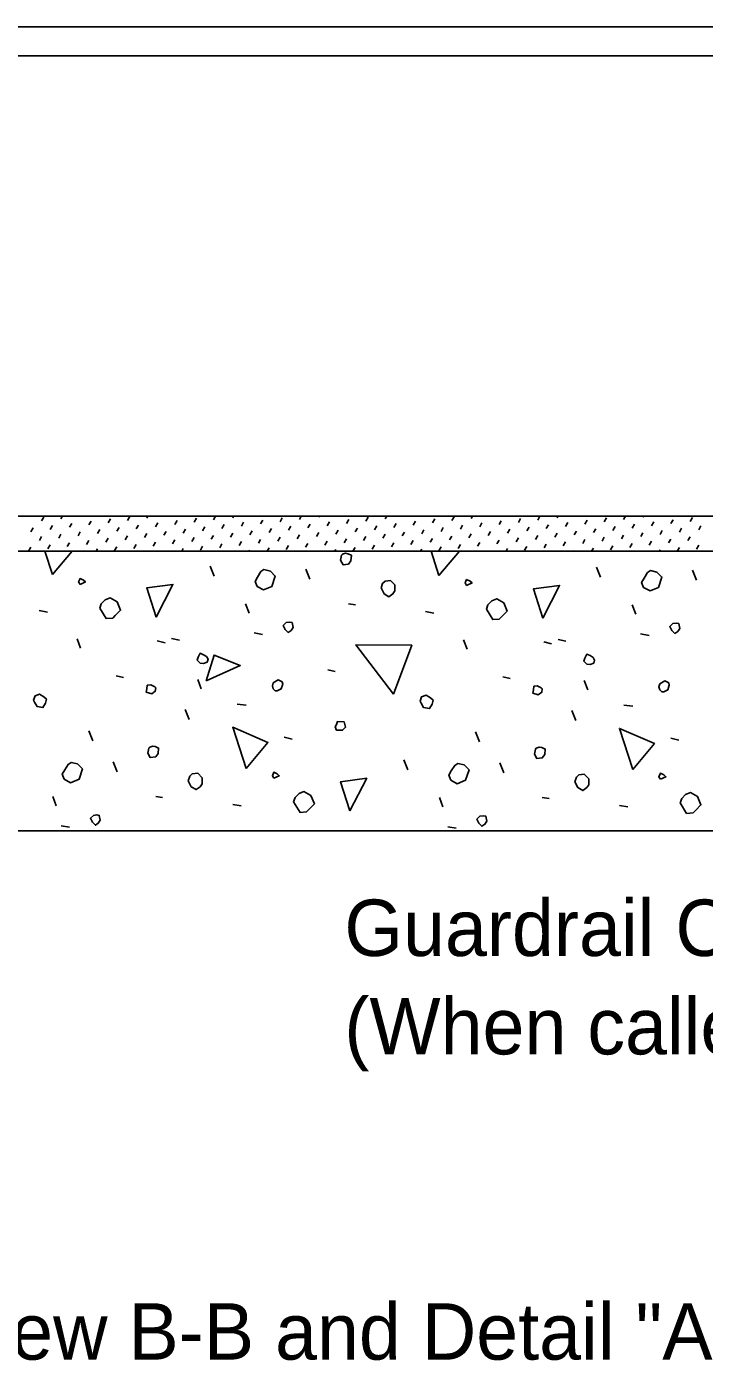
# Model space of a CAD drawing. Extents: x 0.5 to 40.8, y 1 to 25.8.
# Drawn here: x 33.558 to 35.979, y 8.632 to 13.435 of the extents above; entities that cross this region are included whole.
import ezdxf

# ---------------------------------------------------------------- set-up
doc = ezdxf.new("R2010")
doc.units = 0
for name, color, linetype in [('Dimension', 7, 'Continuous'), ('Miscellaneous', 7, 'Continuous'), ('TrafBarrierConc', 7, 'Continuous')]:
    doc.layers.add(name, color=color, linetype=linetype)

msp = doc.modelspace()

# ---------------------------------------------------------------- linework, layer by layer
at = {"layer": 'Miscellaneous'}
for p, q in [((33.6104, 11.6679), (33.6185, 11.6819)), ((33.6796, 11.676), (33.6846, 11.6848)), ((33.7487, 11.6841), (33.7491, 11.6848)), ((33.8484, 11.6617), (33.8565, 11.6757)), ((33.9176, 11.6698), (33.9257, 11.6838)), ((33.9868, 11.6779), (33.9907, 11.6848)), ((34.1556, 11.6636), (34.1637, 11.6776)), ((34.2248, 11.6717), (34.2324, 11.6848)), ((34.2939, 11.6798), (34.2968, 11.6848)), ((34.4628, 11.6654), (34.4709, 11.6794)), ((34.532, 11.6735), (34.5385, 11.6848)), ((34.6011, 11.6816), (34.6029, 11.6848)), ((34.7008, 11.6592), (34.7089, 11.6732)), ((34.77, 11.6673), (34.7781, 11.6813)), ((34.8391, 11.6754), (34.8446, 11.6848)), ((34.9083, 11.6835), (34.909, 11.6848)), ((35.008, 11.6611), (35.0161, 11.6751)), ((35.0772, 11.6692), (35.0853, 11.6832)), ((35.1463, 11.6773), (35.1507, 11.6848)), ((35.3152, 11.663), (35.3233, 11.677)), ((35.3844, 11.6711), (35.3923, 11.6848)), ((35.4535, 11.6792), (35.4568, 11.6848)), ((35.6224, 11.6649), (35.6305, 11.6789)), ((35.6915, 11.673), (35.6984, 11.6848)), ((35.7607, 11.6811), (35.7629, 11.6848)), ((35.8604, 11.6586), (35.8685, 11.6726)), ((35.9296, 11.6667), (35.9377, 11.6807)), ((33.5718, 11.6293), (33.5799, 11.6433)), ((33.6409, 11.6374), (33.649, 11.6514)), ((33.7101, 11.6455), (33.7182, 11.6595)), ((33.7406, 11.615), (33.7487, 11.6289)), ((33.7793, 11.6536), (33.7874, 11.6676)), ((33.8098, 11.6231), (33.8179, 11.6371)), ((33.879, 11.6312), (33.8871, 11.6452)), ((33.9481, 11.6393), (33.9562, 11.6533)), ((34.0173, 11.6474), (34.0254, 11.6614)), ((34.0478, 11.6168), (34.0559, 11.6308)), ((34.0864, 11.6555), (34.0945, 11.6695)), ((34.117, 11.6249), (34.1251, 11.6389)), ((34.1861, 11.633), (34.1942, 11.647)), ((34.2553, 11.6411), (34.2634, 11.6551)), ((34.2858, 11.6106), (34.2939, 11.6246)), ((34.3245, 11.6492), (34.3326, 11.6632)), ((34.355, 11.6187), (34.3631, 11.6327)), ((34.3936, 11.6573), (34.4017, 11.6713)), ((34.4242, 11.6268), (34.4323, 11.6408)), ((34.4933, 11.6349), (34.5014, 11.6489)), ((34.5625, 11.643), (34.5706, 11.657)), ((34.593, 11.6125), (34.6011, 11.6265)), ((34.6317, 11.6511), (34.6398, 11.6651)), ((34.6622, 11.6206), (34.6703, 11.6346)), ((34.7314, 11.6287), (34.7395, 11.6427)), ((34.8005, 11.6368), (34.8086, 11.6508)), ((34.8697, 11.6449), (34.8778, 11.6589)), ((34.9002, 11.6144), (34.9083, 11.6284)), ((34.9388, 11.653), (34.9469, 11.667)), ((34.9694, 11.6225), (34.9775, 11.6365)), ((35.0385, 11.6306), (35.0466, 11.6446)), ((35.1077, 11.6387), (35.1158, 11.6527)), ((35.1769, 11.6468), (35.185, 11.6608)), ((35.2074, 11.6162), (35.2155, 11.6302)), ((35.246, 11.6549), (35.2541, 11.6689)), ((35.2766, 11.6243), (35.2847, 11.6383)), ((35.3457, 11.6324), (35.3538, 11.6464)), ((35.4149, 11.6405), (35.423, 11.6545)), ((35.4841, 11.6487), (35.4922, 11.6626)), ((35.5146, 11.6181), (35.5227, 11.6321)), ((35.5532, 11.6568), (35.5613, 11.6707)), ((35.5837, 11.6262), (35.5918, 11.6402)), ((35.6529, 11.6343), (35.661, 11.6483)), ((35.7221, 11.6424), (35.7302, 11.6564)), ((35.7526, 11.6119), (35.7607, 11.6259)), ((35.7912, 11.6505), (35.7993, 11.6645)), ((35.8218, 11.62), (35.8299, 11.634)), ((35.8909, 11.6281), (35.899, 11.6421)), ((35.9601, 11.6362), (35.9682, 11.6502)), ((33.6023, 11.5987), (33.6104, 11.6127)), ((33.6328, 11.5682), (33.6409, 11.5822)), ((33.6715, 11.6069), (33.6796, 11.6208)), ((33.702, 11.5763), (33.7101, 11.5903)), ((33.7712, 11.5844), (33.7793, 11.5984)), ((33.8403, 11.5925), (33.8484, 11.6065)), ((33.9095, 11.6006), (33.9176, 11.6146)), ((33.94, 11.5701), (33.9481, 11.5841)), ((33.9787, 11.6087), (33.9868, 11.6227)), ((34.0092, 11.5782), (34.0173, 11.5922)), ((34.0783, 11.5863), (34.0864, 11.6003)), ((34.1475, 11.5944), (34.1556, 11.6084)), ((34.178, 11.5639), (34.1861, 11.5779)), ((34.2167, 11.6025), (34.2248, 11.6165)), ((34.2472, 11.572), (34.2553, 11.586)), ((34.3164, 11.5801), (34.3245, 11.5941)), ((34.3855, 11.5882), (34.3936, 11.6022)), ((34.4547, 11.5963), (34.4628, 11.6103)), ((34.4852, 11.5658), (34.4933, 11.5797)), ((34.5239, 11.6044), (34.532, 11.6184)), ((34.5544, 11.5739), (34.5625, 11.5878)), ((34.6236, 11.582), (34.6317, 11.596)), ((34.6927, 11.5901), (34.7008, 11.6041)), ((34.7619, 11.5982), (34.77, 11.6122)), ((34.7924, 11.5676), (34.8005, 11.5816)), ((34.831, 11.6063), (34.8391, 11.6203)), ((34.8616, 11.5757), (34.8697, 11.5897)), ((34.9307, 11.5838), (34.9388, 11.5978)), ((34.9999, 11.5919), (35.008, 11.6059)), ((35.0691, 11.6), (35.0772, 11.614)), ((35.0996, 11.5695), (35.1077, 11.5835)), ((35.1382, 11.6081), (35.1463, 11.6221)), ((35.1688, 11.5776), (35.1769, 11.5916)), ((35.2379, 11.5857), (35.246, 11.5997)), ((35.3071, 11.5938), (35.3152, 11.6078)), ((35.3376, 11.5633), (35.3457, 11.5773)), ((35.3763, 11.6019), (35.3844, 11.6159)), ((35.4068, 11.5714), (35.4149, 11.5854)), ((35.4454, 11.61), (35.4535, 11.624)), ((35.4759, 11.5795), (35.4841, 11.5935)), ((35.5451, 11.5876), (35.5532, 11.6016)), ((35.6143, 11.5957), (35.6224, 11.6097)), ((35.6448, 11.5652), (35.6529, 11.5792)), ((35.6834, 11.6038), (35.6915, 11.6178)), ((35.714, 11.5733), (35.7221, 11.5873)), ((35.7831, 11.5814), (35.7912, 11.5954)), ((35.8523, 11.5895), (35.8604, 11.6035)), ((35.9215, 11.5976), (35.9296, 11.6116)), ((35.952, 11.567), (35.9601, 11.581)), ((33.5637, 11.5601), (33.5718, 11.5741)), ((33.8051, 11.5598), (33.8098, 11.5679)), ((33.8709, 11.562), (33.879, 11.576)), ((34.0467, 11.5598), (34.0478, 11.5617)), ((34.1112, 11.5598), (34.117, 11.5698)), ((34.3528, 11.5598), (34.355, 11.5635)), ((34.4173, 11.5598), (34.4242, 11.5716)), ((34.6589, 11.5598), (34.6622, 11.5654)), ((34.7234, 11.5598), (34.7314, 11.5735)), ((34.965, 11.5598), (34.9694, 11.5673)), ((35.0304, 11.5614), (35.0385, 11.5754)), ((35.2067, 11.5598), (35.2074, 11.5611)), ((35.2711, 11.5598), (35.2766, 11.5692)), ((35.5128, 11.5598), (35.5146, 11.563)), ((35.5772, 11.5598), (35.5837, 11.5711)), ((35.8189, 11.5598), (35.8218, 11.5648)), ((35.8833, 11.5598), (35.8909, 11.5729)), ((34.2268, 11.471), (34.2126, 11.5064)), ((34.5697, 11.4604), (34.5556, 11.4957)), ((35.6092, 11.4675), (35.595, 11.5028)), ((35.9521, 11.4569), (35.938, 11.4922)), ((33.601, 11.3473), (33.631, 11.342)), ((34.3523, 11.3384), (34.3399, 11.372)), ((34.7076, 11.372), (34.7323, 11.3685)), ((34.9834, 11.3437), (35.0134, 11.3384)), ((35.7347, 11.3349), (35.7223, 11.3685)), ((33.7495, 11.2129), (33.7371, 11.2465)), ((34.0747, 11.2483), (34.103, 11.2412)), ((34.3699, 11.2677), (34.4, 11.2624)), ((35.1319, 11.2094), (35.1195, 11.243)), ((35.4571, 11.2447), (35.4854, 11.2377)), ((35.7523, 11.2642), (35.7824, 11.2589)), ((34.0235, 11.2394), (34.0517, 11.2324)), ((35.4059, 11.2359), (35.4341, 11.2288)), ((33.8767, 11.1139), (33.9033, 11.1086)), ((34.1808, 11.0679), (34.1684, 11.1015)), ((34.6333, 11.1351), (34.6599, 11.1298)), ((35.2591, 11.1104), (35.2857, 11.1051)), ((35.5632, 11.0644), (35.5508, 11.098)), ((34.3098, 11.0131), (34.3417, 11.0096)), ((35.6922, 11.0096), (35.7241, 11.0061)), ((34.1384, 10.9583), (34.1242, 10.9937)), ((35.5208, 10.9548), (35.5066, 10.9902)), ((33.7937, 10.8823), (33.7795, 10.9177)), ((35.176, 10.8788), (35.1619, 10.9142)), ((34.4778, 10.8947), (34.5061, 10.8876)), ((35.8602, 10.8912), (35.8885, 10.8841)), ((34.9197, 10.778), (34.9056, 10.8134)), ((33.8803, 10.771), (33.8661, 10.8063)), ((35.2627, 10.7674), (35.2485, 10.8028)), ((33.6628, 10.649), (33.6505, 10.6826)), ((34.0182, 10.6826), (34.0429, 10.679)), ((35.0452, 10.6455), (35.0329, 10.679)), ((35.4006, 10.679), (35.4253, 10.6755)), ((34.2939, 10.6543), (34.324, 10.649)), ((35.6763, 10.6508), (35.7064, 10.6455)), ((33.6805, 10.5783), (33.7106, 10.573)), ((35.0629, 10.5747), (35.093, 10.5694))]:
    msp.add_line(p, q, dxfattribs=at)
for points in [[(33.6487, 11.4763), (33.6215, 11.5598)], [(33.7193, 11.5598), (33.6487, 11.4763)], [(34.6793, 11.5276), (34.6881, 11.5117), (34.7076, 11.5134), (34.7164, 11.5258), (34.7182, 11.5452), (34.7058, 11.5505), (34.697, 11.5523), (34.6864, 11.5488), (34.6828, 11.5452), (34.6793, 11.5276)], [(35.0311, 11.4728), (35.0028, 11.5598)], [(35.1047, 11.5598), (35.0311, 11.4728)], [(34.3806, 11.4339), (34.4035, 11.4215), (34.4336, 11.4339), (34.446, 11.471), (34.4283, 11.4887), (34.4053, 11.494), (34.3947, 11.4869), (34.3823, 11.4675), (34.3735, 11.4516), (34.3806, 11.4339)], [(35.7629, 11.4303), (35.7859, 11.418), (35.816, 11.4303), (35.8284, 11.4675), (35.8107, 11.4851), (35.7877, 11.4904), (35.7771, 11.4834), (35.7647, 11.4639), (35.7559, 11.448), (35.7629, 11.4303)], [(33.7477, 11.4409), (33.7671, 11.4498), (33.7601, 11.4569), (33.7477, 11.4622), (33.7424, 11.4498), (33.7477, 11.4409)], [(34.0199, 11.3243), (33.9863, 11.4286), (34.08, 11.4409), (34.0199, 11.3243)], [(34.8243, 11.4286), (34.8349, 11.4074), (34.8525, 11.3968), (34.8667, 11.4074), (34.8738, 11.418), (34.8738, 11.4392), (34.8579, 11.4551), (34.8384, 11.4533), (34.8296, 11.4445), (34.8243, 11.4286)], [(35.1301, 11.4374), (35.1495, 11.4463), (35.1425, 11.4533), (35.1301, 11.4586), (35.1248, 11.4463), (35.1301, 11.4374)], [(35.4023, 11.3207), (35.3687, 11.425), (35.4624, 11.4374), (35.4023, 11.3207)], [(33.8184, 11.3561), (33.8414, 11.319), (33.8644, 11.3207), (33.8732, 11.3296), (33.8927, 11.349), (33.8803, 11.3791), (33.8555, 11.3932), (33.8378, 11.3861), (33.8237, 11.372), (33.8184, 11.3561)], [(35.2008, 11.3526), (35.2238, 11.3154), (35.2468, 11.3172), (35.2556, 11.326), (35.275, 11.3455), (35.2627, 11.3755), (35.2379, 11.3897), (35.2202, 11.3826), (35.2061, 11.3685), (35.2008, 11.3526)], [(34.4813, 11.2801), (34.4919, 11.2695), (34.5025, 11.2765), (34.5096, 11.2872), (34.5061, 11.3048), (34.4972, 11.3066), (34.4849, 11.3048), (34.4742, 11.2942), (34.4813, 11.2801)], [(35.8637, 11.2765), (35.8743, 11.2659), (35.8849, 11.273), (35.892, 11.2836), (35.8885, 11.3013), (35.8796, 11.3031), (35.8672, 11.3013), (35.8566, 11.2907), (35.8637, 11.2765)], [(34.1773, 11.1599), (34.1896, 11.1581), (34.202, 11.1634), (34.2055, 11.174), (34.2002, 11.1829), (34.1896, 11.1899), (34.1773, 11.1952), (34.1702, 11.1811), (34.1667, 11.1705), (34.1773, 11.1599)], [(34.8685, 11.0485), (34.7341, 11.2253), (34.9339, 11.2235), (34.8685, 11.0485)], [(34.1985, 11.0962), (34.2268, 11.1882), (34.3205, 11.151), (34.1985, 11.0962)], [(35.5597, 11.1563), (35.572, 11.1546), (35.5844, 11.1599), (35.5879, 11.1705), (35.5826, 11.1793), (35.572, 11.1864), (35.5597, 11.1917), (35.5526, 11.1776), (35.549, 11.1669), (35.5597, 11.1563)], [(34.446, 11.0609), (34.453, 11.0609), (34.4672, 11.0679), (34.4725, 11.0839), (34.4707, 11.0927), (34.4566, 11.0998), (34.4389, 11.0892), (34.4354, 11.0786), (34.4389, 11.0679), (34.446, 11.0609)], [(35.8284, 11.0573), (35.8354, 11.0573), (35.8496, 11.0644), (35.8549, 11.0803), (35.8531, 11.0892), (35.839, 11.0962), (35.8213, 11.0856), (35.8177, 11.075), (35.8213, 11.0644), (35.8284, 11.0573)], [(33.5851, 11.0202), (33.5939, 11.0043), (33.6151, 11.0008), (33.624, 11.0167), (33.6275, 11.0308), (33.6186, 11.0397), (33.6027, 11.0485), (33.5868, 11.0432), (33.5815, 11.0273), (33.5851, 11.0202)], [(33.9846, 11.0556), (34.004, 11.0503), (34.0164, 11.0591), (34.0182, 11.0715), (34.0146, 11.075), (34.0005, 11.0821), (33.9881, 11.0803), (33.9863, 11.0679), (33.9846, 11.0556)], [(35.367, 11.052), (35.3864, 11.0467), (35.3988, 11.0556), (35.4006, 11.0679), (35.397, 11.0715), (35.3829, 11.0786), (35.3705, 11.0768), (35.3687, 11.0644), (35.367, 11.052)], [(34.9675, 11.0167), (34.9763, 11.0008), (34.9975, 10.9972), (35.0063, 11.0131), (35.0099, 11.0273), (35.001, 11.0361), (34.9851, 11.045), (34.9692, 11.0397), (34.9639, 11.0238), (34.9675, 11.0167)], [(34.3417, 10.7833), (34.2939, 10.9301), (34.4194, 10.8753), (34.3417, 10.7833)], [(34.6652, 10.9195), (34.6864, 10.9195), (34.697, 10.9301), (34.6917, 10.9495), (34.6687, 10.9513), (34.6652, 10.9407), (34.6599, 10.9318), (34.6652, 10.9195), (34.6616, 10.923)], [(35.7241, 10.7798), (35.6763, 10.9265), (35.8018, 10.8717), (35.7241, 10.7798)], [(33.9899, 10.8381), (33.9987, 10.8222), (34.0182, 10.824), (34.027, 10.8364), (34.0288, 10.8558), (34.0164, 10.8611), (34.0076, 10.8629), (33.9969, 10.8594), (33.9934, 10.8558), (33.9899, 10.8381)], [(35.3723, 10.8346), (35.3811, 10.8187), (35.4006, 10.8205), (35.4094, 10.8328), (35.4112, 10.8523), (35.3988, 10.8576), (35.3899, 10.8594), (35.3793, 10.8558), (35.3758, 10.8523), (35.3723, 10.8346)], [(33.6911, 10.7444), (33.7141, 10.7321), (33.7442, 10.7444), (33.7565, 10.7816), (33.7389, 10.7992), (33.7159, 10.8046), (33.7053, 10.7975), (33.6929, 10.778), (33.6841, 10.7621), (33.6911, 10.7444)], [(34.1348, 10.7391), (34.1454, 10.7179), (34.1631, 10.7073), (34.1773, 10.7179), (34.1843, 10.7285), (34.1843, 10.7498), (34.1684, 10.7657), (34.149, 10.7639), (34.1401, 10.7551), (34.1348, 10.7391)], [(34.4407, 10.748), (34.4601, 10.7568), (34.453, 10.7639), (34.4407, 10.7692), (34.4354, 10.7568), (34.4407, 10.748)], [(35.0735, 10.7409), (35.0965, 10.7285), (35.1266, 10.7409), (35.1389, 10.778), (35.1212, 10.7957), (35.0983, 10.801), (35.0877, 10.7939), (35.0753, 10.7745), (35.0664, 10.7586), (35.0735, 10.7409)], [(35.5172, 10.7356), (35.5278, 10.7144), (35.5455, 10.7038), (35.5597, 10.7144), (35.5667, 10.725), (35.5667, 10.7462), (35.5508, 10.7621), (35.5314, 10.7604), (35.5225, 10.7515), (35.5172, 10.7356)], [(35.8231, 10.7444), (35.8425, 10.7533), (35.8354, 10.7604), (35.8231, 10.7657), (35.8177, 10.7533), (35.8231, 10.7444)], [(34.7129, 10.6313), (34.6793, 10.7356), (34.773, 10.748), (34.7129, 10.6313)], [(34.5114, 10.6631), (34.5344, 10.626), (34.5573, 10.6278), (34.5662, 10.6366), (34.5856, 10.6561), (34.5732, 10.6861), (34.5485, 10.7003), (34.5308, 10.6932), (34.5167, 10.679), (34.5114, 10.6631)], [(35.8938, 10.6596), (35.9167, 10.6225), (35.9397, 10.6242), (35.9486, 10.6331), (35.968, 10.6525), (35.9556, 10.6826), (35.9309, 10.6967), (35.9132, 10.6896), (35.8991, 10.6755), (35.8938, 10.6596)], [(33.7919, 10.5907), (33.8025, 10.58), (33.8131, 10.5871), (33.8202, 10.5977), (33.8166, 10.6154), (33.8078, 10.6172), (33.7954, 10.6154), (33.7848, 10.6048), (33.7919, 10.5907)], [(35.1743, 10.5871), (35.1849, 10.5765), (35.1955, 10.5836), (35.2026, 10.5942), (35.199, 10.6119), (35.1902, 10.6136), (35.1778, 10.6119), (35.1672, 10.6013), (35.1743, 10.5871)]]:
    msp.add_lwpolyline(points, dxfattribs=at)
at = {"layer": 'TrafBarrierConc'}
for p, q in [((23.987, 13.4349), (37.3177, 13.4349)), ((23.987, 13.3307), (37.3177, 13.3307)), ((23.987, 11.6848), (39.8181, 11.6848)), ((23.987, 11.5598), (39.8181, 11.5598)), ((23.987, 10.5598), (39.8181, 10.5598))]:
    msp.add_line(p, q, dxfattribs=at)

# ---------------------------------------------------------------- texts
at = {"layer": 'Dimension'}
for s, p in [('Guardrail Connection', (34.6929, 10.1125)), ('(When called for in Plans)', (34.6929, 9.7605)), ('  For Section A-A, End View B-B and Detail "A" see Sheet 2.', (30.5047, 8.669))]:
    msp.add_text(s, height=0.2016, dxfattribs=at).set_placement(p)

doc.saveas('drawing.dxf')
